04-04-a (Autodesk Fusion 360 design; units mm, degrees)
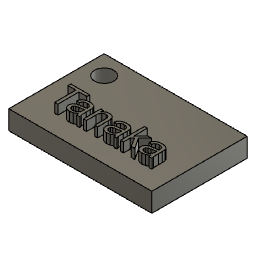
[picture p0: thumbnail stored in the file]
sketch "スケッチ2" plane through (0, 0, 0) normal (0, 1, 0) x axis (1, 0, 0)
  line L1 (-15, 10) -> (15, 10)
  line L2 (-15, -10) -> (-15, 10)
  line L3 (15, -10) -> (-15, -10)
  line L4 (15, 10) -> (15, -10)
  line L5 (-15, -10) -> (15, 10)
  line L6 (15, -10) -> (-15, 10)
  point P6 (0, 0)
  point P1 (0, 0)
  point P2 (15, 10)
  point P3 (-15, 10)
  point P5 (15, -10)
  horizontal L1
  perpendicular L1 L2
  parallel L1 L3
  parallel L2 L4
  coincident L5 P6
  coincident L6 P6
  coincident P1 P6
  dimension "d5" distance P2 P3 = 30
  dimension "d6" distance P2 P5 = 20
extrude "押し出し2" new body sketch "スケッチ2" profile of L1 L2 L3 L4 along normal blind 4
hole "穴" HoleDepth 4 HoleDiameter 4 TipAngle 118 RefDim1 4 RefDim2 4
sketch "スケッチ3" plane through (0, 4, 0) normal (0, 1, 0) x axis (-1, 0, 0)
  dimension "d14" = 5
  dimension "d15" = 4
  dimension "d16" = 11
extrude "押し出し3" add sketch "スケッチ3" along normal blind 2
